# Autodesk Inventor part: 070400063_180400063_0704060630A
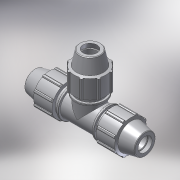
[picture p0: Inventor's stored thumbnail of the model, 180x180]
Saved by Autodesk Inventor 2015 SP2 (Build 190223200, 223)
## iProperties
Created: 2017-02
Part Number: 070400063_180400063_0704060630A
Material: PVC-Piping
Description: PLASSON TEE 63-63-63
Document SubType Name: Modeling
Designer: KIM
Mass: 92.6774 g
Surface Area: 199.44 cm^2
Volume: 66.1981 cm^3
Density: 1.4 g/cm^3
Appearance: Smooth - White
Author: KIM
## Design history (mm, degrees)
derived "07040.ipt"
feature "Solid1::07040.ipt"
tag "TaggingFeature1"
body "Solid1"
other parameters: "d2" = 63, "d4" = 12.16667, "d5" = 36.5, "d7" = 113, "d11" = 4.86667, "d13" = 120 deg, "d14" = 81.9, "d15" = 12 deg, "d16" = 98.31, "d18" = 3.15, "d19" = 35 deg, "d20" = 17.5 deg, "d21" = 105.09, "d23" = 0, "d25" = 360 deg, "d27" = 2.26, "d33" = 1.26, "d42" = 51.1, "d43" = 3.39, "d46" = 1.89, "d67" = 84.75, "d76" = 63, "d77" = 113, "d78" = 12 deg, "d79" = 146, "d80" = 120 deg, "d81" = 81.9, "d82" = 12.16667, "d85" = 84.75, "d86" = 98.31, "d87" = 4.86667, "d88" = 4.86667, "d89" = 36.5, "d90" = 51.1, "d96" = 14.6, "d98" = 105.09, "d99" = 35 deg, "d100" = 17.5 deg, "d102" = 0, "d103" = 2.26, "d107" = 360 deg, "d109" = 1.89, "d112" = 3.15, "d118" = 360 deg, "d121" = 0, "d128" = 294, "d131" = 56.7, "d132" = 56.7, "d134" = 2.2, "d135" = 14.6, "d152" = 0, "d154" = 0, "d156" = 0, "d158" = 0, "d_" = 63, "E_" = 113, "A_" = 146, "H_" = 294
